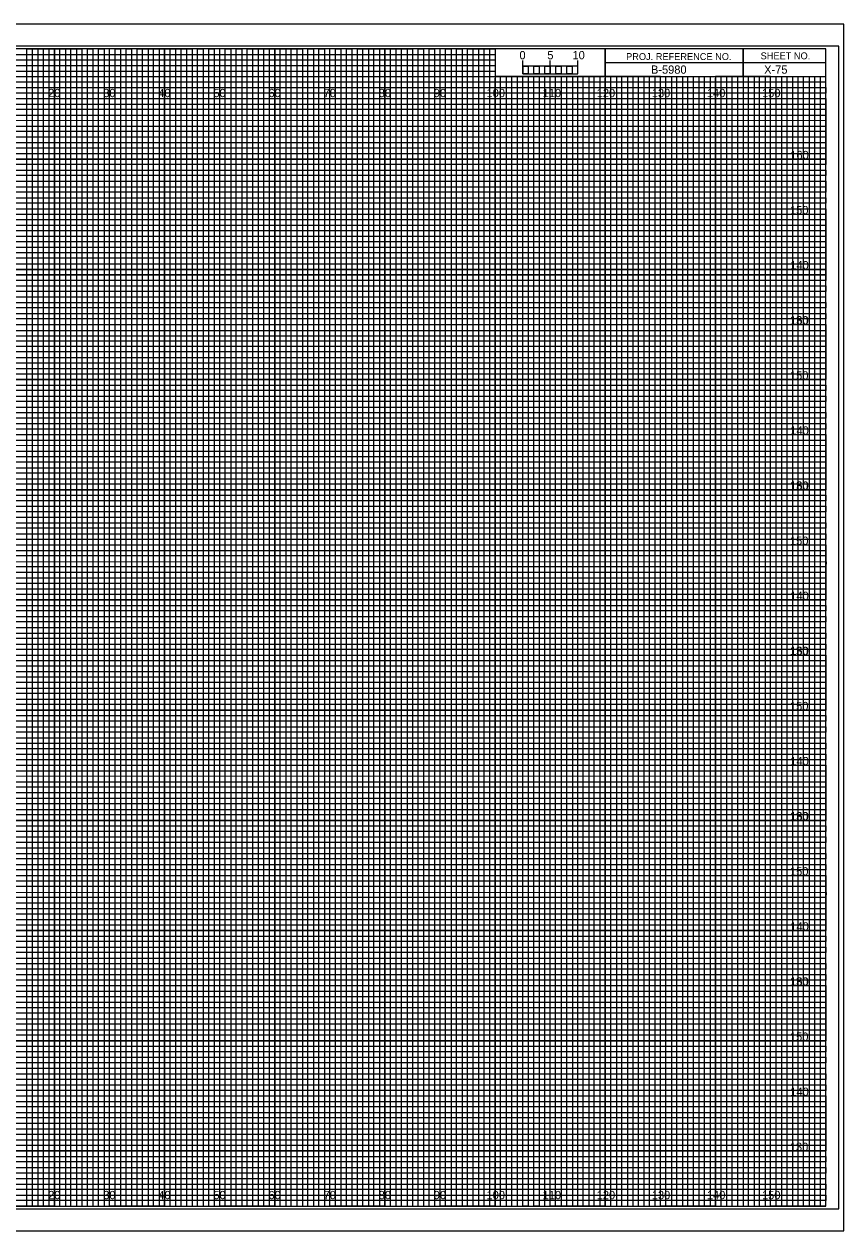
# Model space of a CAD drawing. Extents: x -13 to 323, y -5 to 654.
# Drawn here: x 174.5 to 323.3, y 215.5 to 434.5 of the extents above; entities that cross this region are included whole.
import ezdxf

# ---------------------------------------------------------------- set-up
doc = ezdxf.new("R2010")
doc.units = 0
for name, color, linetype in [('Exist Cross Section Cell', 7, 'Continuous'), ('Exist XS Center Line Elevation Label', 7, 'Continuous'), ('Exist XS Ground Line', 7, 'Continuous'), ('Prop CMT Guardrail Graphics', 7, 'Continuous'), ('Prop CMT Guardrail Widen Shoulder', 7, 'Continuous'), ('Prop CMT Pvmt Course 1', 7, 'Continuous'), ('Prop CMT Pvmt Course 2', 7, 'Continuous'), ('Prop CMT Pvmt Surface', 7, 'Continuous'), ('Prop CMT Shld Paved Course 1', 7, 'Continuous'), ('Prop CMT Shld Paved Course 2', 7, 'Continuous'), ('Prop CMT Shld Paved Course 3', 7, 'Continuous'), ('Prop CMT Slope Grass', 7, 'Continuous'), ('Prop CMT Subgrade Earthwork', 7, 'Continuous'), ('Prop Retaining Wall', 7, 'Continuous'), ('Prop XS Earthwork Shape', 7, 'Continuous')]:
    doc.layers.add(name, color=color, linetype=linetype)

msp = doc.modelspace()

# ---------------------------------------------------------------- linework, layer by layer
at = {"layer": 'Exist XS Center Line Elevation Label'}
for points in [[(165, 220), (175, 220), (175, 430), (185, 430), (185, 220), (195, 220), (195, 430), (205, 430), (205, 220), (215, 220), (215, 430), (225, 430), (225, 220), (235, 220), (235, 430), (245, 430), (245, 220), (255, 220), (255, 430), (259.93, 430), (260, 430), (260, 425), (264.99, 425), (264.99, 220), (275, 220), (275, 425), (285, 425), (285, 220), (295, 220), (295, 425), (305, 425), (305, 220), (315, 220), (315, 425)], [(0, 425), (275, 425)], [(0, 405), (320, 405), (320, 415), (0, 415)], [(0, 385), (320, 385), (320, 395), (0, 395)], [(0, 365), (320, 365), (320, 375), (0, 375)], [(0, 345), (320, 345), (320, 355), (0, 355)], [(0, 325), (320, 325), (320, 335), (0, 335)], [(0, 305), (320, 305), (320, 315), (0, 315)], [(0, 285), (320, 285), (320, 295), (0, 295)], [(0, 265), (320, 265), (320, 275), (0, 275)], [(0, 245), (320, 245), (320, 255), (0, 255)], [(0, 225), (320, 225), (320, 235), (0, 235)]]:
    msp.add_lwpolyline(points, dxfattribs=at)
at = {"layer": 'Exist XS Ground Line'}
for p, q in [((190, 430), (180, 430)), ((180, 430), (180, 220)), ((190, 220), (190, 430)), ((210, 430), (200, 430)), ((200, 430), (200, 220)), ((210, 220), (210, 430)), ((230, 430), (220, 430)), ((220, 430), (220, 220)), ((230, 220), (230, 430)), ((250, 430), (240, 430)), ((240, 430), (240, 220)), ((250, 220), (250, 430)), ((260, 430), (260, 220)), ((270, 220), (270, 425)), ((290, 425), (280, 425)), ((280, 425), (280, 220)), ((290, 220), (290, 425)), ((310, 425), (300, 425)), ((300, 425), (300, 220)), ((310, 220), (310, 425)), ((180, 220), (170, 220)), ((200, 220), (190, 220)), ((220, 220), (210, 220)), ((240, 220), (230, 220)), ((260, 220), (250, 220)), ((280, 220), (270, 220)), ((300, 220), (290, 220)), ((320, 220), (310, 220)), ((320, 220), (320, 220))]:
    msp.add_line(p, q, dxfattribs=at)
for points in [[(0, 420), (320, 420), (320, 410), (0, 410)], [(0, 400), (320, 400), (320, 390), (0, 390)], [(0, 380), (320, 380), (320, 370), (0, 370)], [(0, 360), (320, 360), (320, 350), (0, 350)], [(0, 340), (320, 340), (320, 330), (0, 330)], [(0, 320), (320, 320), (320, 310), (0, 310)], [(0, 300), (320, 300), (320, 290), (0, 290)], [(0, 280), (320, 280), (320, 270), (0, 270)], [(0, 260), (320, 260), (320, 250), (0, 250)], [(0, 240), (320, 240), (320, 230), (0, 230)]]:
    msp.add_lwpolyline(points, dxfattribs=at)
at = {"layer": 'Prop CMT Pvmt Course 1'}
for p, q in [((0, 429), (260, 429)), ((260, 427.98), (0, 427.98)), ((260, 429), (260, 427.98)), ((0, 427), (260, 427)), ((260, 425.89), (0, 425.89)), ((260, 427), (260, 425.89)), ((0, 424), (320, 424))]:
    msp.add_line(p, q, dxfattribs=at)
for points in [[(0, 423), (270, 423), (320, 423), (320, 422), (0, 422)], [(0, 421), (320, 421), (320, 419), (0, 419)], [(0, 418), (320, 418), (320, 417), (0, 416.98)], [(0, 416), (320, 416), (320, 414), (0, 414)], [(0, 413), (320, 413), (320, 412), (0, 412)], [(0, 411), (320, 411), (320, 409), (0, 409)], [(0, 408), (320, 408), (320, 407), (0, 407)], [(0, 406), (320, 406), (320, 404), (0, 404)], [(0, 403), (320, 403), (320, 402), (0, 402)], [(0, 401), (320, 401), (320, 399), (0, 399)], [(0, 398), (320, 398), (320, 397), (0, 397)], [(0, 396), (320, 396), (320, 393.95), (320, 393), (320, 392), (0, 392)], [(0, 394), (320, 394), (320, 393), (0, 393)], [(0, 391), (320, 391), (320, 389), (0, 389.03)], [(0, 389.03), (320, 389), (320, 388), (0, 388)], [(0, 387), (320, 387), (320, 386), (0, 386)], [(0, 384), (320, 384), (320, 383), (0, 383)], [(0, 382), (320, 382), (320, 381), (0, 381)], [(-0.07, 378.89), (320, 378.89), (320, 377.88), (-0.07, 377.88)], [(0, 377), (320, 377), (320, 376), (0, 376)], [(0, 374), (320, 374), (320, 373), (0, 373)], [(0, 372), (320, 372), (320, 371), (0, 371)], [(0, 369), (320, 369), (320, 368), (0, 368)], [(0, 367), (320, 367), (320, 366), (0, 366)], [(0, 364), (320, 364), (320, 363), (0, 363)], [(0, 362), (320, 362), (320, 361), (0, 361)], [(0, 359), (320, 359), (319.99, 357.98), (0, 358)], [(0, 357), (320, 357), (320, 356), (0, 356)], [(0, 354), (320, 354), (320, 353), (0, 353)], [(0, 352), (320, 352), (320, 351), (0, 351)], [(0, 349), (320, 349), (320, 348), (0, 348)], [(0, 347), (320, 347), (320, 346), (0, 346)], [(0, 344), (320, 344), (320, 343), (0, 343)], [(0, 342), (320, 342), (320, 341), (0, 341)], [(0, 339), (320, 339), (320, 338), (0, 338)], [(0, 336.99), (320.07, 336.91), (320, 336), (0, 336)], [(0, 334), (320, 334), (320, 333), (0, 333)], [(0, 332), (320, 332), (320, 331), (0, 331)], [(0, 329), (320, 329), (320, 328), (0, 328)], [(0, 327), (320, 327), (320, 326), (0, 326)], [(0, 324), (320, 324), (320, 323), (0, 323)], [(0, 322), (320, 322), (320, 321), (0, 321)], [(0, 319), (320, 319), (320, 318), (0, 318)], [(0, 317), (320, 317), (320, 316), (0, 316)], [(0, 314), (320, 314), (320, 313), (0, 313)], [(0, 312), (320, 312), (320, 311), (0, 311)], [(0, 309), (320, 309), (320, 308), (0, 308)], [(0, 307), (320, 307), (320, 306), (0, 306)], [(0, 304), (320, 304), (320, 303), (0, 303)], [(0, 302), (320, 302), (320, 301), (0, 301)], [(0, 299), (320, 299), (319.99, 297.98), (0, 298)], [(0, 297), (320, 297), (320, 296), (0, 296)], [(0, 294), (320, 294), (320, 293), (0, 293)], [(0, 292), (320, 292), (320, 291), (0, 291)], [(0, 289), (320, 289), (320, 288), (0, 288)], [(0, 287), (320, 287), (320, 286), (0, 286)], [(0, 284), (320, 284), (320, 283), (0, 283)], [(0, 282), (320, 282), (320, 281), (0, 281)], [(0, 279), (320, 279), (320, 278), (0, 278)], [(0, 276.99), (320.07, 276.91), (320, 276), (0, 276)], [(0, 274), (320, 274), (320, 273), (0, 273)], [(0, 272), (320, 272), (320, 271), (0, 271)], [(0, 269), (320, 269), (320, 268), (0, 268)], [(0, 267), (320, 267), (320, 266), (0, 266)], [(0, 264), (320, 264), (320, 263), (0, 263)], [(0, 262), (320, 262), (320, 261), (0, 261)], [(0, 259), (320, 259), (320, 258), (0, 258)], [(0, 257), (320, 257), (320, 256), (0, 256)], [(0, 254), (320, 254), (320, 253), (0, 253)], [(0, 252), (320, 252), (320, 251), (0, 251)], [(0, 249), (320, 249), (320, 248), (0, 248)], [(0, 247), (320, 247), (320, 246), (0, 246)], [(0, 244), (320, 244), (320, 243), (0, 243)], [(0, 242), (320, 242), (320, 241), (0, 241)], [(0, 239), (320, 239), (320, 238), (0, 238)], [(0, 237), (320, 237), (320, 236), (0, 236)], [(0, 234), (320, 234), (320, 233), (0, 233)], [(0, 232), (320, 232), (320, 231), (0, 231)], [(0, 229), (320, 229), (320, 228), (0, 228)], [(0, 227), (320, 227), (320, 226), (0, 226)], [(0, 224), (320, 224), (320, 223), (0, 223)], [(0, 222), (320, 222), (320, 221), (0, 221)]]:
    msp.add_lwpolyline(points, dxfattribs=at)
at = {"layer": 'Prop CMT Pvmt Surface'}
for p, q in [((267, 425), (266.01, 425)), ((266.01, 425), (266.01, 220)), ((267, 220), (267, 425)), ((269, 425), (268, 425)), ((268, 425), (268, 220)), ((269, 220), (269, 425)), ((266.01, 220), (265, 220)), ((268, 220), (267, 220))]:
    msp.add_line(p, q, dxfattribs=at)
for points in [[(175, 220), (176, 220), (176, 430), (177, 430), (177, 220)], [(177, 220), (178, 220), (178, 430), (179, 430), (179, 220)], [(180, 220), (181, 220), (181, 430), (182, 430), (182, 220)], [(182, 220), (183, 220), (183, 430), (184, 430), (184, 220)], [(185, 220), (186, 220), (186, 430), (187, 430), (187, 220)], [(187, 220), (188, 220), (188, 430), (189, 430), (189, 220)], [(190, 220), (191, 220), (191, 430), (192, 430), (192, 220)], [(192, 220), (193, 220), (193, 430), (194, 430), (194, 220)], [(195, 220), (196, 220), (196, 430), (197, 430), (197, 220)], [(197, 220), (198, 220), (198, 430), (199, 430), (199, 220)], [(200, 220), (201, 220), (201, 430), (202, 430), (202, 220)], [(202, 220), (203, 220), (203, 430), (204, 430), (204, 220)], [(205, 220), (206, 220), (206, 430), (207, 430), (207, 220)], [(207, 220), (208, 220), (208, 430), (209, 430), (209, 220)], [(210, 220), (211, 220), (211, 430), (212, 430), (212, 220)], [(212, 220), (213, 220), (213, 430), (214, 430), (214, 220)], [(215, 220), (216, 220), (216, 430), (217, 430), (217, 220)], [(217, 220), (218, 220), (218, 430), (219, 430), (219, 220)], [(220, 220), (221, 220), (221, 430), (222, 430), (222, 220)], [(222, 220), (223, 220), (223, 430), (224, 430), (224, 220)], [(225, 220), (226, 220), (226, 430), (227, 430), (227, 220)], [(227, 220), (228, 220), (228, 430), (229, 430), (229, 220)], [(230, 220), (231, 220), (231, 430), (232, 430), (232, 220)], [(232, 220), (233, 220), (233, 430), (234, 430), (234, 220)], [(235, 220), (236, 220), (236, 430), (237, 430), (237, 220)], [(237, 220), (238, 220), (238, 430), (239, 430), (239, 220)], [(240, 220), (241, 220), (241, 430), (242, 430), (242, 220)], [(242, 220), (243, 220), (243, 430), (244, 430), (244, 220)], [(245, 220), (246, 220), (246, 430), (247, 430), (247, 220)], [(247, 220), (248, 220), (248, 430), (249, 430), (249, 220)], [(250, 220), (251, 220), (251, 430), (252, 430), (252, 220)], [(252, 220), (253, 220), (253, 430), (254, 430), (254, 220)], [(255, 220), (256, 220), (256, 430), (257, 430), (257, 220)], [(257, 220), (258, 220), (258, 430), (259, 430), (259, 220)], [(260, 220), (261, 220), (261, 425), (262.02, 425), (262.02, 220)], [(262, 220), (263, 220), (263, 425), (263.99, 425), (263.99, 220)], [(270, 220), (270.98, 220), (270.98, 425), (272, 425), (272, 220)], [(272, 220), (273, 220), (273, 425), (274.05, 425), (274.05, 220)], [(275, 220), (276, 220), (276, 425), (277, 425), (277, 220)], [(277, 220), (278, 220), (278, 425), (279, 425), (279, 220)], [(280, 220), (281, 220), (281, 425), (282, 425), (282, 220)], [(282, 220), (283, 220), (283, 425), (284, 425), (284, 220)], [(285, 220), (286, 220), (286, 425), (287, 425), (287, 220)], [(287, 220), (288, 220), (288, 425), (289, 425), (289, 220)], [(290, 220), (291, 220), (291, 425), (292, 425), (292, 220)], [(292, 220), (293, 220), (293, 425), (294, 425), (294, 220)], [(295, 220), (296, 220), (296, 425), (297, 425), (297, 220)], [(297, 220), (298, 220), (298, 425), (299, 425), (299, 220)], [(300, 220), (301, 220), (301, 425), (302, 425), (302, 220)], [(302, 220), (303, 220), (303, 425), (304, 425), (304, 220)], [(305, 220), (306, 220), (306, 425), (307, 425), (307, 220)], [(307, 220), (308, 220), (308, 425), (309, 425), (309, 220)], [(310, 220), (311, 220), (311, 425), (312, 425), (312, 220)], [(312, 220), (313, 220), (313, 425), (314, 425), (314, 220)], [(315, 220), (316, 220), (316, 425), (317, 425), (317, 220)], [(317, 220), (318, 220), (318, 425), (319, 425), (319, 220)]]:
    msp.add_lwpolyline(points, dxfattribs=at)
at = {"layer": 'Prop CMT Shld Paved Course 1'}
msp.add_lwpolyline([(-10.8, 219.5), (322.4, 219.5), (322.4, 430.5), (-10.8, 430.5)], close=True, dxfattribs=at)
at = {"layer": 'Prop CMT Shld Paved Course 2'}
for p, q in [((180, 220), (180, 430)), ((190, 220), (190, 430)), ((200, 220), (200, 430)), ((210, 220), (210, 430)), ((220, 220), (220, 430)), ((230, 220), (230, 430)), ((240, 220), (240, 430)), ((250, 220), (250, 430)), ((260, 220), (260, 424.69)), ((270, 220), (270, 424.69)), ((280, 220), (280, 424.69)), ((290, 220), (290, 424.69)), ((300, 220), (300, 424.69)), ((310, 220), (310, 424.69)), ((0, 420), (320, 420)), ((0, 410), (320, 410)), ((0, 400), (320, 400)), ((0, 390), (320, 390)), ((0, 380), (320, 380)), ((0, 370), (320, 370)), ((0, 360), (320, 360)), ((0, 350), (320, 350)), ((0, 340), (320, 340)), ((0, 330), (320, 330)), ((0, 320), (320, 320)), ((0, 310), (320, 310)), ((0, 300), (320, 300)), ((0, 290), (320, 290)), ((0, 280), (320, 280)), ((0, 270), (320, 270)), ((0, 260), (320, 260)), ((0, 250), (320, 250)), ((0, 240), (320, 240)), ((0, 230), (320, 230))]:
    msp.add_line(p, q, dxfattribs=at)
at = {"layer": 'Prop CMT Shld Paved Course 3'}
for p, q in [((323.3, 434.5), (-13.4, 434.5)), ((-13.4, 215.5), (323.3, 215.5))]:
    msp.add_line(p, q, dxfattribs=at)
at = {"layer": 'Prop CMT Slope Grass'}
for p, q in [((305, 430), (305, 425)), ((305, 425), (305, 430)), ((280, 427.5), (280, 425)), ((320, 427.49), (280, 427.49)), ((280, 425), (320, 425))]:
    msp.add_line(p, q, dxfattribs=at)
for points in [[(320, 430), (0, 430), (0, 220), (320, 220)], [(280, 430), (260, 430), (260, 425.03), (280, 425.03)], [(320, 430), (280, 430), (280, 425), (320, 425)]]:
    msp.add_lwpolyline(points, close=True, dxfattribs=at)
at = {"layer": 'Prop Retaining Wall'}
for p, q in [((265, 425.49), (265, 427.9)), ((265, 426.9), (265, 427.9)), ((270, 425.49), (270, 427.9)), ((275, 425.49), (275, 427.9)), ((275, 426.9), (275, 427.9))]:
    msp.add_line(p, q, dxfattribs=at)
for points in [[(275, 426.9), (265, 426.9), (265, 425.49), (275, 425.49)], [(265, 426.9), (266, 426.9), (266, 425.49), (265, 425.49)], [(267, 426.9), (268, 426.9), (268, 425.49), (267, 425.49)], [(269, 426.9), (270, 426.9), (270, 425.49), (269, 425.49)], [(271, 426.9), (272, 426.9), (272, 425.49), (271, 425.49)], [(273, 426.9), (274, 426.9), (274, 425.49), (273, 425.49)]]:
    msp.add_lwpolyline(points, close=True, dxfattribs=at)
at = {"layer": 'Prop XS Earthwork Shape'}
msp.add_lwpolyline([(-13.4, 215.5), (323.3, 215.5), (323.3, 434.5), (-13.4, 434.5)], close=True, dxfattribs=at)

# ---------------------------------------------------------------- texts
at = {"layer": 'Exist Cross Section Cell'}
for s, p in [('20', (178.86, 421.25)), ('30', (188.86, 421.25)), ('40', (198.86, 421.25)), ('50', (208.86, 421.25)), ('60', (218.86, 421.25)), ('70', (228.86, 421.25)), ('80', (238.86, 421.25)), ('90', (248.86, 421.25)), ('100', (258.44, 421.25)), ('110', (268.62, 421.25)), ('120', (278.44, 421.25)), ('130', (288.44, 421.25)), ('140', (298.44, 421.25)), ('150', (308.44, 421.25)), ('20', (178.86, 221.25)), ('30', (188.86, 221.25)), ('40', (198.86, 221.25)), ('50', (208.86, 221.25)), ('60', (218.86, 221.25)), ('70', (228.86, 221.25)), ('80', (238.86, 221.25)), ('90', (248.86, 221.25)), ('100', (258.44, 221.25)), ('110', (268.62, 221.25)), ('120', (278.44, 221.25)), ('130', (288.44, 221.25)), ('140', (298.44, 221.25)), ('150', (308.44, 221.25))]:
    msp.add_text(s, height=1.5, dxfattribs=at).set_placement(p)
at = {"layer": 'Prop CMT Guardrail Graphics'}
msp.add_text('B-5980', height=1.5, dxfattribs=at).set_placement((288.28, 425.5))
at = {"layer": 'Prop CMT Guardrail Widen Shoulder'}
for s, p in [('5', (269.47, 428.12)), ('10', (274.04, 428.12))]:
    msp.add_text(s, height=1.5, dxfattribs=at).set_placement(p)
at = {"layer": 'Prop CMT Pvmt Course 2'}
for s, p in [('160', (313.57, 410)), ('150', (313.52, 400)), ('140', (313.57, 390)), ('130', (313.49, 380)), ('160', (313.57, 380)), ('150', (313.52, 370)), ('140', (313.57, 360)), ('130', (313.49, 350)), ('160', (313.57, 350)), ('150', (313.52, 340)), ('140', (313.57, 330)), ('130', (313.49, 320)), ('160', (313.57, 320)), ('150', (313.52, 310)), ('140', (313.57, 300)), ('130', (313.49, 290)), ('160', (313.57, 290)), ('150', (313.52, 280)), ('140', (313.57, 270)), ('130', (313.49, 260)), ('160', (313.57, 260)), ('150', (313.52, 250)), ('140', (313.57, 240)), ('130', (313.49, 230))]:
    msp.add_text(s, height=1.5, dxfattribs=at).set_placement(p)
at = {"layer": 'Prop CMT Slope Grass'}
for s, p in [('PROJ. REFERENCE NO.', (283.77, 427.99)), ('SHEET NO.', (308.19, 428.12))]:
    msp.add_text(s, height=1.25, dxfattribs=at).set_placement(p)
at = {"layer": 'Prop CMT Subgrade Earthwork'}
msp.add_text('X-75', height=1.5, dxfattribs=at).set_placement((308.83, 425.5))
at = {"layer": 'Prop Retaining Wall'}
msp.add_text('0', height=1.5, dxfattribs=at).set_placement((264.41, 428.12))

doc.saveas('drawing.dxf')
